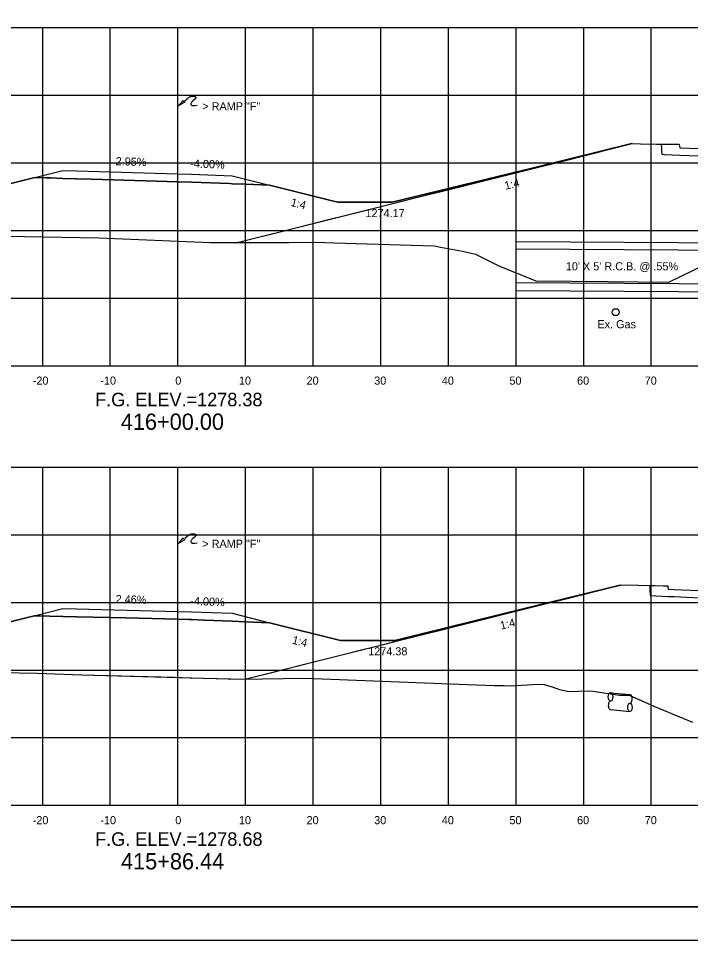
# Model space of a CAD drawing. Extents: x 2148105 to 2149976, y 144169 to 149705.
# Drawn here: x 2148389.7 to 2148489.1, y 146836.9 to 146973.3 of the extents above; entities that cross this region are included whole.
import ezdxf

# ---------------------------------------------------------------- set-up
doc = ezdxf.new("R2010")
doc.units = 0
for name, color, linetype in [('Bridge M-Header', 7, 'Continuous'), ('Default', 7, 'Continuous'), ('INR_Tracking', 7, 'Continuous'), ('Ph1-PR-Ramp SF3 Rev-Curb', 7, 'Continuous'), ('PH1a-2-RampC', 7, 'Continuous'), ('PH1a-PR-DividingStrip', 7, 'Continuous'), ('PH1a-PR-ServRd', 7, 'Continuous'), ('PH2-PR-Barrier', 7, 'Continuous'), ('PR-ApproachSlab', 7, 'Continuous'), ('PR-SHLDR-RMP-H', 7, 'Continuous'), ('PR_Align_Ramp_J', 7, 'Continuous'), ('PR_Storm_Channel', 7, 'Continuous'), ('PR_Storm_Conc_Box_PH1B', 7, 'Continuous'), ('PR_Storm_Conc_Pipe_PH1B', 7, 'Continuous'), ('PR_Storm_Inlet_CICI_PH1B', 7, 'Continuous'), ('PR_Storm_Junction_Box_PH1A', 7, 'Continuous'), ('PR_Storm_Junction_Box_PH1B', 7, 'Continuous'), ('PR_Storm_MH_PH1B', 7, 'Continuous'), ('PR_Storm_Standard_Median_Drain_PH1B', 7, 'Continuous'), ('TopCut', 7, 'Continuous')]:
    doc.layers.add(name, color=color, linetype=linetype)

# ---------------------------------------------------------------- blocks, each defined once
blk = doc.blocks.new('POINT_DISPLAY')
at = {"layer": 'Default'}
blk.add_line((0, 0), (0, 0), dxfattribs=at)

msp = doc.modelspace()

# ---------------------------------------------------------------- linework, layer by layer
at = {"layer": 'INR_Tracking'}
for points in [[(2148378, 146946.21), (2148392.15, 146949.75), (2148393.83, 146949.7), (2148394.33, 146949.68), (2148394.49, 146949.68), (2148396.32, 146949.62), (2148398.21, 146949.57), (2148398.32, 146949.56), (2148398.32, 146949.56), (2148400.56, 146949.5), (2148413.32, 146949.12), (2148413.32, 146949.12), (2148415.32, 146949.06), (2148415.32, 146949.06), (2148420.97, 146948.84), (2148421.32, 146948.82), (2148423.31, 146948.74), (2148423.31, 146948.74), (2148424.5, 146948.7), (2148426.88, 146948.6), (2148435.72, 146946.39), (2148436.98, 146946.08), (2148437.44, 146946.08), (2148444.97, 146946.08), (2148444.98, 146946.08), (2148445.01, 146946.08), (2148465.7, 146951.14), (2148480.43, 146954.75), (2148480.47, 146954.76)], [(2148380.84, 146882.13), (2148392.08, 146884.94), (2148392.08, 146884.94), (2148392.91, 146884.92), (2148394.33, 146884.89), (2148394.33, 146884.89), (2148396.32, 146884.84), (2148396.32, 146884.84), (2148396.33, 146884.84), (2148398.32, 146884.79), (2148398.35, 146884.79), (2148405.6, 146884.61), (2148413.32, 146884.42), (2148414.92, 146884.38), (2148415.32, 146884.37), (2148417.23, 146884.29), (2148421.32, 146884.13), (2148421.32, 146884.13), (2148421.32, 146884.13), (2148423.31, 146884.05), (2148423.31, 146884.05), (2148426.88, 146883.91), (2148437.37, 146881.28), (2148437.39, 146881.28), (2148445.38, 146881.28), (2148445.39, 146881.28), (2148445.4, 146881.29), (2148464.39, 146885.95), (2148478.74, 146889.48), (2148478.77, 146889.49)]]:
    msp.add_lwpolyline(points, dxfattribs=at)
at = {"layer": 'Ph1-PR-Ramp SF3 Rev-Curb'}
for p, q in [((2148477.29, 146873.56), (2148480.16, 146873.27)), ((2148477.29, 146871.06), (2148480.16, 146870.77))]:
    msp.add_line(p, q, dxfattribs=at)
for points in [[(2148463.32, 146940.29), (2148503.32, 146940.04)], [(2148463.32, 146939.21), (2148503.32, 146938.96)], [(2148463.32, 146934.21), (2148503.32, 146933.96)], [(2148463.32, 146933.04), (2148503.32, 146932.79)]]:
    msp.add_lwpolyline(points, dxfattribs=at)
for centre, start_param, end_param in [((2148477.29, 146871.69), 6.283185, 9.424778), ((2148480.16, 146872.64), 3.141592, 6.283185)]:
    msp.add_ellipse(centre, major_axis=(0, 0.625), ratio=0.523109, start_param=start_param, end_param=end_param, dxfattribs=at)
for centre in [(2148477.29, 146872.94), (2148480.16, 146871.39)]:
    msp.add_ellipse(centre, major_axis=(0, 0.625), ratio=0.523109, dxfattribs=at)
at = {"layer": 'PH1a-PR-ServRd'}
msp.add_lwpolyline([(2148570.82, 146841.91), (2148255.82, 146841.91), (2148255.82, 147051.91), (2148570.82, 147051.91)], close=True, dxfattribs=at)
at = {"layer": 'PH2-PR-Barrier'}
for p, q in [((2148413.32, 146950.29), (2148413.32, 146960.29)), ((2148413.32, 146885.59), (2148413.32, 146895.59))]:
    msp.add_line(p, q, dxfattribs=at)
for points in [[(2148413.32, 146960.29), (2148413.84, 146960.84), (2148414.1, 146961.15), (2148414.18, 146960.98), (2148414.32, 146960.86), (2148413.32, 146960.29)], [(2148414.33, 146961.1), (2148414.69, 146961.39), (2148414.85, 146961.52), (2148414.94, 146961.59), (2148415.04, 146961.65), (2148415.14, 146961.7), (2148415.26, 146961.73), (2148415.39, 146961.76), (2148415.49, 146961.77), (2148415.57, 146961.77), (2148415.65, 146961.77), (2148415.72, 146961.75), (2148415.78, 146961.74), (2148415.83, 146961.72), (2148415.87, 146961.69), (2148415.91, 146961.66), (2148415.95, 146961.62), (2148415.98, 146961.56), (2148415.97, 146961.5), (2148415.96, 146961.46), (2148415.91, 146961.39), (2148415.72, 146961.23), (2148415.53, 146961.07), (2148415.46, 146960.99), (2148415.39, 146960.92), (2148415.33, 146960.82), (2148415.29, 146960.76), (2148415.25, 146960.67), (2148415.25, 146960.6), (2148415.27, 146960.51), (2148415.31, 146960.44), (2148415.36, 146960.41), (2148415.42, 146960.38), (2148415.53, 146960.37), (2148415.66, 146960.38), (2148415.82, 146960.39), (2148416.15, 146960.43)], [(2148414.33, 146896.4), (2148414.69, 146896.69), (2148414.85, 146896.82), (2148414.94, 146896.89), (2148415.04, 146896.95), (2148415.14, 146896.99), (2148415.26, 146897.03), (2148415.39, 146897.06), (2148415.49, 146897.07), (2148415.57, 146897.07), (2148415.65, 146897.06), (2148415.72, 146897.05), (2148415.78, 146897.04), (2148415.83, 146897.02), (2148415.87, 146896.99), (2148415.91, 146896.96), (2148415.95, 146896.91), (2148415.98, 146896.86), (2148415.97, 146896.8), (2148415.96, 146896.76), (2148415.91, 146896.69), (2148415.72, 146896.53), (2148415.53, 146896.37), (2148415.46, 146896.29), (2148415.39, 146896.22), (2148415.33, 146896.12), (2148415.29, 146896.06), (2148415.25, 146895.97), (2148415.25, 146895.89), (2148415.27, 146895.81), (2148415.31, 146895.74), (2148415.36, 146895.71), (2148415.42, 146895.68), (2148415.53, 146895.67), (2148415.66, 146895.67), (2148415.82, 146895.69), (2148416.15, 146895.73)], [(2148413.32, 146895.59), (2148413.84, 146896.14), (2148414.1, 146896.44), (2148414.18, 146896.28), (2148414.32, 146896.16), (2148413.32, 146895.59)]]:
    msp.add_lwpolyline(points, dxfattribs=at)
at = {"layer": 'PR-ApproachSlab'}
for points in [[(2148422.06, 146940.13), (2148429.23, 146941.92), (2148430.95, 146942.35), (2148440.83, 146944.83), (2148443.89, 146945.6), (2148450.77, 146947.32), (2148452.25, 146947.69), (2148459.35, 146949.47), (2148463.48, 146950.5), (2148473.1, 146952.91), (2148474.2, 146953.19), (2148474.53, 146953.27), (2148480.47, 146954.76), (2148481.74, 146954.73), (2148484.04, 146954.69), (2148484.8, 146954.68), (2148485.07, 146954.68), (2148486.85, 146954.65), (2148486.86, 146954.65), (2148486.86, 146954.65), (2148487.09, 146954.65), (2148487.45, 146954.65), (2148487.5, 146954.37), (2148487.53, 146954.15), (2148487.54, 146954.15), (2148487.54, 146954.15), (2148490.23, 146954.03)], [(2148423.2, 146875.56), (2148468, 146886.79), (2148478.77, 146889.49), (2148481.44, 146889.44), (2148483.09, 146889.41), (2148483.79, 146889.4), (2148485.14, 146889.37), (2148485.15, 146889.37), (2148485.15, 146889.37), (2148485.67, 146889.38), (2148485.74, 146889.38), (2148485.75, 146889.32), (2148485.83, 146888.88), (2148485.83, 146888.88), (2148486.63, 146888.84), (2148491.42, 146888.63)]]:
    msp.add_lwpolyline(points, dxfattribs=at)
at = {"layer": 'PR-SHLDR-RMP-H'}
for points in [[(2148422.06, 146940.13), (2148427.22, 146941.42), (2148428.06, 146941.63), (2148435.6, 146943.52), (2148437.8, 146944.07), (2148443.9, 146945.6), (2148447.41, 146946.48), (2148452.1, 146947.65), (2148455.45, 146948.49), (2148458.03, 146949.14), (2148459.41, 146949.48), (2148460.22, 146949.68), (2148466.25, 146951.2), (2148468.24, 146951.69), (2148475.49, 146953.51), (2148476.18, 146953.68), (2148480.47, 146954.76), (2148481.74, 146954.73), (2148484.04, 146954.69), (2148484.8, 146954.68), (2148484.8, 146954.38), (2148484.81, 146954.35), (2148484.82, 146954.35), (2148484.82, 146954.35), (2148484.82, 146954.26), (2148484.84, 146953.52), (2148484.85, 146953.22), (2148484.85, 146953.18), (2148485.28, 146953.16), (2148487.53, 146953.06), (2148487.54, 146953.06), (2148487.54, 146953.06), (2148490.23, 146952.94)], [(2148423.2, 146875.56), (2148425.56, 146876.16), (2148426.01, 146876.27), (2148434.6, 146878.42), (2148435.6, 146878.67), (2148439.12, 146879.55), (2148440.48, 146879.89), (2148443.52, 146880.66), (2148447.34, 146881.61), (2148452.35, 146882.87), (2148457.75, 146884.22), (2148461.06, 146885.05), (2148468.01, 146886.79), (2148469.69, 146887.21), (2148478.1, 146889.32), (2148478.2, 146889.34), (2148478.77, 146889.49), (2148481.44, 146889.44), (2148483.09, 146889.41), (2148483.09, 146889.22), (2148483.1, 146889.08), (2148483.1, 146889.08), (2148483.11, 146889.08), (2148483.12, 146888.59), (2148483.14, 146888.24), (2148483.14, 146888.05), (2148483.15, 146887.91), (2148483.99, 146887.87), (2148485.83, 146887.79), (2148485.83, 146887.79), (2148486.63, 146887.76), (2148491.42, 146887.54)]]:
    msp.add_lwpolyline(points, dxfattribs=at)
at = {"layer": 'PR_Align_Ramp_J'}
msp.add_lwpolyline([(2148236.32, 147056.91), (2148576.32, 147056.91), (2148576.32, 146836.91), (2148236.32, 146836.91)], close=True, dxfattribs=at)
at = {"layer": 'PR_Storm_Channel'}
for points in [[(2148392.15, 146949.75), (2148396.32, 146950.79), (2148398.32, 146950.73), (2148413.32, 146950.29), (2148415.32, 146950.23), (2148421.32, 146949.99), (2148426.88, 146948.6)], [(2148392.08, 146884.94), (2148396.32, 146886), (2148398.32, 146885.96), (2148413.32, 146885.59), (2148415.32, 146885.54), (2148421.32, 146885.3), (2148426.88, 146883.91)]]:
    msp.add_lwpolyline(points, dxfattribs=at)
at = {"layer": 'PR_Storm_Conc_Box_PH1B'}
for p, q in [((2148263.32, 146971.91), (2148563.32, 146971.91)), ((2148393.32, 146921.91), (2148393.32, 146971.91)), ((2148403.32, 146921.91), (2148403.32, 146971.91)), ((2148413.32, 146921.91), (2148413.32, 146971.91)), ((2148423.32, 146921.91), (2148423.32, 146971.91)), ((2148433.32, 146921.91), (2148433.32, 146971.91)), ((2148443.32, 146921.91), (2148443.32, 146971.91)), ((2148453.32, 146921.91), (2148453.32, 146971.91)), ((2148463.32, 146921.91), (2148463.32, 146971.91)), ((2148473.32, 146921.91), (2148473.32, 146971.91)), ((2148483.32, 146921.91), (2148483.32, 146971.91)), ((2148263.32, 146961.91), (2148563.32, 146961.91)), ((2148263.32, 146951.91), (2148563.32, 146951.91)), ((2148263.32, 146941.91), (2148563.32, 146941.91)), ((2148263.32, 146931.91), (2148563.32, 146931.91)), ((2148263.32, 146921.91), (2148563.32, 146921.91)), ((2148263.32, 146906.91), (2148563.32, 146906.91)), ((2148393.32, 146856.91), (2148393.32, 146906.91)), ((2148403.32, 146856.91), (2148403.32, 146906.91)), ((2148413.32, 146856.91), (2148413.32, 146906.91)), ((2148423.32, 146856.91), (2148423.32, 146906.91)), ((2148433.32, 146856.91), (2148433.32, 146906.91)), ((2148443.32, 146856.91), (2148443.32, 146906.91)), ((2148453.32, 146856.91), (2148453.32, 146906.91)), ((2148463.32, 146856.91), (2148463.32, 146906.91)), ((2148473.32, 146856.91), (2148473.32, 146906.91)), ((2148483.32, 146856.91), (2148483.32, 146906.91)), ((2148263.32, 146896.91), (2148563.32, 146896.91)), ((2148263.32, 146886.91), (2148563.32, 146886.91)), ((2148263.32, 146876.91), (2148563.32, 146876.91)), ((2148263.32, 146866.91), (2148563.32, 146866.91)), ((2148263.32, 146856.91), (2148563.32, 146856.91))]:
    msp.add_line(p, q, dxfattribs=at)
at = {"layer": 'PR_Storm_Conc_Pipe_PH1B'}
msp.add_lwpolyline([(2148255.82, 146841.91), (2148570.82, 146841.91), (2148570.82, 147051.91), (2148255.82, 147051.91)], close=True, dxfattribs=at)
msp.add_lwpolyline([(2148255.82, 146841.91), (2148570.82, 146841.91), (2148570.82, 147051.91), (2148255.82, 147051.91)], close=True, dxfattribs=at)
at = {"layer": 'PR_Storm_Inlet_CICI_PH1B'}
for points in [[(2148382.44, 146941.13), (2148390.62, 146941.04), (2148401.62, 146940.82), (2148418.12, 146940.13), (2148429.76, 146940.11), (2148433.67, 146940.17), (2148436.4, 146940.06), (2148447.86, 146939.74), (2148451.24, 146939.63), (2148452.13, 146939.46), (2148455.38, 146938.86), (2148457.31, 146938.41), (2148460.76, 146936.7), (2148466.24, 146934.44), (2148476.95, 146934.36), (2148485.89, 146934.29), (2148491.5, 146936.99)], [(2148387.85, 146876.53), (2148389.84, 146876.51), (2148392.51, 146876.45), (2148399.05, 146876.18), (2148422.59, 146875.56), (2148432.12, 146875.69), (2148457.4, 146874.7), (2148460.07, 146874.63), (2148461.54, 146874.61), (2148462.58, 146874.58), (2148466.58, 146874.84), (2148467.47, 146874.76), (2148468.8, 146874.36), (2148469.76, 146874.04), (2148471.1, 146873.73), (2148474.02, 146873.84), (2148474.68, 146873.78), (2148478.6, 146873.18), (2148480.02, 146873.17), (2148483.69, 146871.58), (2148489.43, 146869.21)]]:
    msp.add_lwpolyline(points, dxfattribs=at)
at = {"layer": 'PR_Storm_Junction_Box_PH1A'}
msp.add_circle((2148478.05, 146929.83), 0.516, dxfattribs=at)
at = {"layer": 'PR_Storm_Standard_Median_Drain_PH1B'}
for p, q in [((2148263.32, 146921.91), (2148563.32, 146921.91)), ((2148263.32, 146856.91), (2148563.32, 146856.91))]:
    msp.add_line(p, q, dxfattribs=at)
at = {"layer": 'TopCut'}
for points in [[(2148382.44, 146941.13), (2148390.62, 146941.04), (2148401.62, 146940.82), (2148418.12, 146940.13), (2148421.23, 146940.13), (2148421.45, 146940.13), (2148421.78, 146940.13), (2148422.06, 146940.13), (2148427.22, 146941.42), (2148428.06, 146941.63), (2148435.6, 146943.52), (2148437.8, 146944.07), (2148443.9, 146945.6), (2148447.41, 146946.48), (2148452.1, 146947.65), (2148455.45, 146948.49), (2148458.03, 146949.14), (2148459.41, 146949.48), (2148460.22, 146949.68), (2148466.25, 146951.2), (2148468.24, 146951.69), (2148475.49, 146953.51), (2148476.18, 146953.68), (2148480.47, 146954.76), (2148480.43, 146954.75), (2148465.7, 146951.14), (2148445.01, 146946.08), (2148444.98, 146946.08), (2148444.97, 146946.08), (2148437.44, 146946.08), (2148436.98, 146946.08), (2148435.72, 146946.39), (2148426.88, 146948.6), (2148424.5, 146948.7), (2148423.31, 146948.74), (2148423.31, 146948.74), (2148421.32, 146948.82), (2148420.97, 146948.84), (2148415.32, 146949.06), (2148415.32, 146949.06), (2148413.32, 146949.12), (2148413.32, 146949.12), (2148400.56, 146949.5), (2148398.32, 146949.56), (2148398.32, 146949.56), (2148398.21, 146949.57), (2148396.32, 146949.62), (2148394.49, 146949.68), (2148394.33, 146949.68), (2148393.83, 146949.7), (2148392.15, 146949.75), (2148378, 146946.21)], [(2148387.85, 146876.53), (2148389.84, 146876.51), (2148392.51, 146876.45), (2148399.05, 146876.18), (2148412.83, 146875.84), (2148415.1, 146875.78), (2148421.15, 146875.62), (2148423.2, 146875.56), (2148425.56, 146876.16), (2148426.01, 146876.27), (2148434.6, 146878.42), (2148435.6, 146878.67), (2148439.12, 146879.55), (2148440.48, 146879.89), (2148443.52, 146880.66), (2148447.34, 146881.61), (2148452.35, 146882.87), (2148457.75, 146884.22), (2148461.06, 146885.05), (2148468.01, 146886.79), (2148469.69, 146887.21), (2148474.85, 146888.5), (2148475.24, 146888.6), (2148478.17, 146889.34), (2148478.2, 146889.34), (2148478.69, 146889.47), (2148464.39, 146885.95), (2148445.4, 146881.29), (2148445.39, 146881.28), (2148445.38, 146881.28), (2148437.39, 146881.28), (2148437.37, 146881.28), (2148426.88, 146883.91), (2148423.31, 146884.05), (2148423.31, 146884.05), (2148421.32, 146884.13), (2148421.32, 146884.13), (2148421.32, 146884.13), (2148417.23, 146884.29), (2148415.32, 146884.37), (2148414.92, 146884.38), (2148413.32, 146884.42), (2148405.6, 146884.61), (2148398.35, 146884.79), (2148398.32, 146884.79), (2148396.33, 146884.84), (2148396.32, 146884.84), (2148396.32, 146884.84), (2148394.33, 146884.89), (2148394.33, 146884.89), (2148392.91, 146884.92), (2148392.08, 146884.94), (2148392.08, 146884.94), (2148380.84, 146882.13)]]:
    msp.add_lwpolyline(points, dxfattribs=at)

# ---------------------------------------------------------------- block references
at = {"layer": 'PR_Storm_Conc_Pipe_PH1B', "xscale": 10, "yscale": 10}
for p in [(2148398.32, 146950.73), (2148398.32, 146950.73), (2148415.32, 146950.23), (2148415.32, 146950.23), (2148421.32, 146949.99), (2148421.32, 146949.99), (2148398.32, 146885.96), (2148398.32, 146885.96), (2148415.32, 146885.54), (2148415.32, 146885.54), (2148421.32, 146885.3), (2148421.32, 146885.3)]:
    msp.add_blockref('POINT_DISPLAY', p, dxfattribs=at)

# ---------------------------------------------------------------- texts
at = {"layer": 'Bridge M-Header'}
for s, rotation, p in [('2.95%', 358.3107, (2148404.1, 146951.56)), ('-4.00%', 357.7094, (2148415.13, 146951.24)), ('2.46%', 358.5902, (2148404.1, 146886.81)), ('-4.00%', 357.7094, (2148415.13, 146886.55))]:
    msp.add_text(s, height=1.2, rotation=rotation, dxfattribs=at).set_placement(p)
at = {"layer": 'PH1a-2-RampC'}
for s, p in [('1274.17', (2148441.05, 146943.88)), ("10' X 5' R.C.B. @ .55%", (2148470.68, 146936.01)), ('1274.38', (2148441.45, 146879.08))]:
    msp.add_text(s, height=1.2, dxfattribs=at).set_placement(p)
at = {"layer": 'PH1a-PR-DividingStrip'}
for rotation, p in [(13.7413, (2148461.76, 146947.92)), (345.9647, (2148429.92, 146945.57)), (13.8073, (2148461.12, 146882.88)), (345.9605, (2148430.12, 146880.83))]:
    msp.add_text('1:4', height=1.2, rotation=rotation, dxfattribs=at).set_placement(p)
at = {"layer": 'PH2-PR-Barrier'}
for p in [(2148416.92, 146959.68), (2148416.92, 146894.98)]:
    msp.add_text('> RAMP "F"', height=1.2, rotation=360, dxfattribs=at).set_placement(p)
at = {"layer": 'PR_Storm_Junction_Box_PH1A'}
msp.add_text('Ex. Gas', height=1.2, rotation=360, dxfattribs=at).set_placement((2148475.35, 146927.45))
at = {"layer": 'PR_Storm_Junction_Box_PH1B'}
for s, p in [('416+00.00', (2148404.87, 146912.43)), ('415+86.44', (2148404.9, 146847.43))]:
    msp.add_text(s, height=2.4, dxfattribs=at).set_placement(p)
at = {"layer": 'PR_Storm_MH_PH1B'}
for s, height, p in [('-20', 1.2, (2148391.85, 146919.11)), ('-10', 1.2, (2148401.85, 146919.11)), ('0', 1.2, (2148412.93, 146919.11)), ('10', 1.2, (2148422.34, 146919.11)), ('20', 1.2, (2148432.34, 146919.11)), ('30', 1.2, (2148442.34, 146919.11)), ('40', 1.2, (2148452.34, 146919.11)), ('50', 1.2, (2148462.34, 146919.11)), ('60', 1.2, (2148472.34, 146919.11)), ('70', 1.2, (2148482.34, 146919.11)), ('F.G. ELEV.=1278.38', 2, (2148401.07, 146915.91)), ('-20', 1.2, (2148391.85, 146854.11)), ('-10', 1.2, (2148401.85, 146854.11)), ('0', 1.2, (2148412.93, 146854.11)), ('10', 1.2, (2148422.34, 146854.11)), ('20', 1.2, (2148432.34, 146854.11)), ('30', 1.2, (2148442.34, 146854.11)), ('40', 1.2, (2148452.34, 146854.11)), ('50', 1.2, (2148462.34, 146854.11)), ('60', 1.2, (2148472.34, 146854.11)), ('70', 1.2, (2148482.34, 146854.11)), ('F.G. ELEV.=1278.68', 2, (2148401.07, 146850.91))]:
    msp.add_text(s, height=height, dxfattribs=at).set_placement(p)

doc.saveas('drawing.dxf')
